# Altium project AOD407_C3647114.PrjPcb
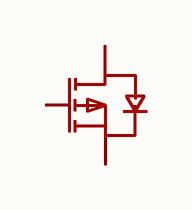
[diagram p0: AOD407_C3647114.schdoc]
1 sheet, 1 parts. Net scope: global (net labels, ports and power ports of the same name join across sheets).

## Sheet AOD407_C3647114.schdoc
size 127 x 101 mm

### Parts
Q?  aod407-ms  [TO-252-2_L6.6-W6.0-P4.58-LS10.1-BR]  (value not drawn)

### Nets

Not connected (* = marked no-connect by the designer): Q? 1(G) 2(D) 3(S)

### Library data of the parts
Q? = aod407-ms: 数量:1个P沟道;漏源电压(Vdss):60V;连续漏极电流(Id):12A;导通电阻(RDS(on)):90mΩ@10V;耗散功率(Pd):30W;阈值电压(Vgs(th)):1.6V;; Manufacturer: MSKSEMI(美森科); Symbol: AOD407_C3647114; AddInBom: yes; ModelId: 15201b043553414fa3153da7281ca125; ModelTransform: 259.842,395.6685,0,90,0,0,-38.543,0,0; Number: 1个P沟道; Drain to Source Voltage: 60V; Current - Continuous Drain(Id): 12A; Pd - Power Dissipation: 30W; Gate Threshold Voltage (Vgs(th)): 1.6V; Gate Charge(Qg): 16.4nC@10V; Input Capacitance(Ciss): 970pF; Reverse Transfer Capacitance (Crss@Vds): 42pF; Type: P沟道; Output Capacitance(Coss): 100pF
